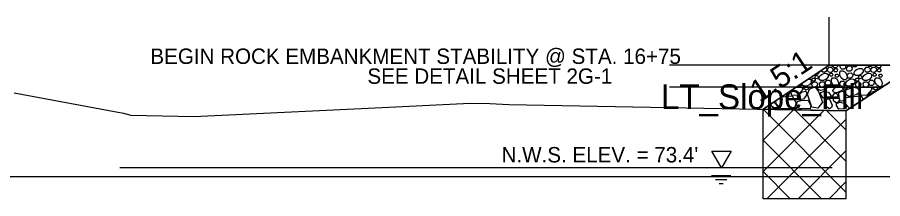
# Model space of a CAD drawing. Extents: x -14026 to 1303, y -10 to 9533.
# Drawn here: x 82.55 to 121.9, y 2999 to 3007.24 of the extents above; entities that cross this region are included whole.
import ezdxf

# ---------------------------------------------------------------- set-up
doc = ezdxf.new("R2010")
doc.units = 0
for name, color, linetype in [('Exist Cross Section Cell', 7, 'Continuous'), ('Exist XS Ground Line', 7, 'Continuous'), ('Old_Level_10', 7, 'Continuous'), ('Prop XS Side Slope Text', 7, 'Continuous'), ('Scratch_Level_0', 7, 'Continuous'), ('Scratch_Level_1', 7, 'Continuous'), ('Scratch_Level_3', 7, 'Continuous'), ('Scratch_Level_5', 7, 'Continuous')]:
    doc.layers.add(name, color=color, linetype=linetype)

msp = doc.modelspace()

# ---------------------------------------------------------------- linework, layer by layer
at = {"layer": 'Exist Cross Section Cell'}
msp.add_line((0, 3000), (150, 3000), dxfattribs=at)
at = {"layer": 'Exist XS Ground Line'}
msp.add_lwpolyline([(82.41, 3003.808), (87.387, 3002.891), (87.708, 3002.797), (90.58, 3002.733), (99.144, 3003.149), (103.146, 3003.333), (104.045, 3003.328), (104.909, 3003.285), (120.234, 3002.995), (122.366, 3004.389)], dxfattribs=at)
at = {"layer": 'Old_Level_10'}
for p, q in [((119.976, 3005.021), (120.008, 3005.067)), ((117.689, 3003.879), (117.714, 3003.824)), ((117.97, 3004.067), (121.872, 3004.067)), ((120.001, 3003), (120.001, 3003))]:
    msp.add_line(p, q, dxfattribs=at)
msp.add_lwpolyline([(116.47, 3003.067), (119.47, 3005.067), (123.495, 3005.067), (122.366, 3004.389), (120.234, 3002.995)], close=True, dxfattribs=at)
for points in [[(119.307, 3004.958), (119.36, 3004.903), (119.35, 3004.794), (119.283, 3004.739), (119.177, 3004.747), (119.127, 3004.795), (119.12, 3004.833)], [(119.417, 3005.031), (119.392, 3005.005), (119.378, 3005.006)], [(119.388, 3004.874), (119.455, 3004.97), (119.562, 3004.976), (119.637, 3004.899), (119.626, 3004.79), (119.56, 3004.735), (119.454, 3004.743), (119.404, 3004.791), (119.388, 3004.874)], [(119.849, 3005.067), (119.843, 3004.999), (119.791, 3004.944), (119.697, 3004.946), (119.591, 3005.029), (119.572, 3005.067)], [(120.204, 3005.067), (120.225, 3005.045), (120.214, 3004.937), (120.148, 3004.881), (120.042, 3004.889), (119.992, 3004.938), (119.976, 3005.021)], [(120.26, 3004.926), (120.327, 3005.021), (120.434, 3005.027), (120.509, 3004.95), (120.498, 3004.842), (120.432, 3004.787), (120.326, 3004.794), (120.276, 3004.843), (120.26, 3004.926)], [(120.742, 3005.067), (120.74, 3005.044), (120.688, 3004.989), (120.594, 3004.991), (120.497, 3005.067)], [(121.012, 3005.067), (120.993, 3005.051), (120.887, 3005.059), (120.879, 3005.067)], [(121.09, 3004.878), (121.157, 3004.974), (121.264, 3004.98), (121.339, 3004.903), (121.328, 3004.794), (121.262, 3004.739), (121.156, 3004.747), (121.106, 3004.795), (121.09, 3004.878)], [(121.424, 3005.067), (121.423, 3005.06), (121.371, 3005.005), (121.277, 3005.007), (121.201, 3005.067)], [(121.366, 3004.874), (121.434, 3004.97), (121.541, 3004.976), (121.616, 3004.899), (121.605, 3004.79), (121.539, 3004.735), (121.433, 3004.743), (121.383, 3004.791), (121.367, 3004.874)], [(121.828, 3005.067), (121.822, 3004.999), (121.77, 3004.944), (121.676, 3004.946), (121.569, 3005.029), (121.551, 3005.067)], [(119.031, 3004.774), (119.031, 3004.763), (118.947, 3004.657), (118.819, 3004.593), (118.757, 3004.591)], [(118.827, 3004.533), (118.867, 3004.59), (118.931, 3004.594), (118.976, 3004.547), (118.97, 3004.482), (118.93, 3004.449), (118.866, 3004.454), (118.836, 3004.483), (118.827, 3004.533)], [(119.126, 3004.645), (119.252, 3004.695), (119.368, 3004.685), (119.423, 3004.633), (119.421, 3004.539), (119.338, 3004.432), (119.209, 3004.368), (119.087, 3004.366), (119.019, 3004.414), (119.013, 3004.511), (119.068, 3004.597), (119.131, 3004.648)], [(119.486, 3004.643), (119.526, 3004.7), (119.59, 3004.704), (119.635, 3004.658), (119.629, 3004.593), (119.589, 3004.559), (119.525, 3004.564), (119.495, 3004.593), (119.486, 3004.643)], [(119.694, 3004.845), (119.734, 3004.902), (119.798, 3004.906), (119.843, 3004.859), (119.837, 3004.794), (119.797, 3004.761), (119.733, 3004.766), (119.703, 3004.795), (119.694, 3004.845)], [(119.75, 3004.596), (119.791, 3004.653), (119.855, 3004.657), (119.9, 3004.61), (119.893, 3004.545), (119.854, 3004.512), (119.79, 3004.517), (119.76, 3004.546), (119.75, 3004.596)], [(120.232, 3004.7), (120.282, 3004.574), (120.272, 3004.458), (120.22, 3004.403), (120.126, 3004.405), (120.02, 3004.488), (119.955, 3004.617), (119.953, 3004.739), (120.002, 3004.807), (120.099, 3004.813), (120.185, 3004.758), (120.236, 3004.694)], [(120.29, 3004.611), (120.357, 3004.707), (120.464, 3004.713), (120.539, 3004.635), (120.528, 3004.527), (120.462, 3004.472), (120.356, 3004.48), (120.306, 3004.528), (120.29, 3004.611)], [(120.715, 3004.87), (120.841, 3004.919), (120.956, 3004.909), (121.011, 3004.857), (121.009, 3004.763), (120.926, 3004.657), (120.797, 3004.593), (120.676, 3004.59), (120.608, 3004.639), (120.601, 3004.736), (120.657, 3004.822), (120.72, 3004.873)], [(120.805, 3004.533), (120.846, 3004.59), (120.91, 3004.594), (120.955, 3004.547), (120.948, 3004.482), (120.909, 3004.449), (120.845, 3004.454), (120.815, 3004.483), (120.805, 3004.533)], [(121.105, 3004.645), (121.231, 3004.695), (121.346, 3004.685), (121.401, 3004.633), (121.4, 3004.539), (121.316, 3004.432), (121.187, 3004.368), (121.066, 3004.366), (120.998, 3004.414), (120.991, 3004.511), (121.047, 3004.597), (121.11, 3004.648)], [(121.464, 3004.643), (121.505, 3004.7), (121.569, 3004.704), (121.614, 3004.658), (121.607, 3004.593), (121.568, 3004.559), (121.504, 3004.564), (121.474, 3004.593), (121.464, 3004.643)], [(121.672, 3004.845), (121.713, 3004.902), (121.777, 3004.906), (121.822, 3004.859), (121.815, 3004.794), (121.776, 3004.761), (121.712, 3004.766), (121.682, 3004.795), (121.672, 3004.845)], [(121.729, 3004.596), (121.769, 3004.653), (121.834, 3004.657), (121.879, 3004.61), (121.872, 3004.545), (121.832, 3004.512), (121.769, 3004.517), (121.739, 3004.546), (121.729, 3004.596)], [(118.216, 3004.23), (118.209, 3004.157), (118.142, 3004.102), (118.036, 3004.11), (118.036, 3004.11)], [(118.523, 3004.435), (118.599, 3004.429), (118.654, 3004.376), (118.652, 3004.283), (118.569, 3004.176), (118.44, 3004.112), (118.319, 3004.11), (118.25, 3004.158), (118.244, 3004.249)], [(118.684, 3004.206), (118.751, 3004.301), (118.858, 3004.308), (118.933, 3004.23), (118.922, 3004.122), (118.856, 3004.067), (118.75, 3004.074), (118.7, 3004.123), (118.684, 3004.206)], [(118.688, 3004.416), (118.728, 3004.473), (118.793, 3004.477), (118.838, 3004.431), (118.831, 3004.366), (118.791, 3004.332), (118.728, 3004.337), (118.698, 3004.366), (118.688, 3004.416)], [(119.03, 3004.21), (119.098, 3004.305), (119.205, 3004.311), (119.28, 3004.234), (119.269, 3004.126), (119.202, 3004.071), (119.096, 3004.078), (119.047, 3004.127), (119.03, 3004.21)], [(119.291, 3004.28), (119.358, 3004.376), (119.466, 3004.382), (119.54, 3004.304), (119.53, 3004.196), (119.463, 3004.141), (119.357, 3004.148), (119.307, 3004.197), (119.291, 3004.28)], [(119.852, 3004.382), (119.902, 3004.257), (119.892, 3004.141), (119.84, 3004.086), (119.746, 3004.088), (119.639, 3004.171), (119.575, 3004.3), (119.573, 3004.421), (119.621, 3004.49), (119.718, 3004.496), (119.805, 3004.441), (119.855, 3004.377)], [(119.949, 3004.241), (120.016, 3004.337), (120.123, 3004.343), (120.198, 3004.266), (120.187, 3004.157), (120.121, 3004.102), (120.015, 3004.11), (119.965, 3004.158), (119.949, 3004.241)], [(120.337, 3004.389), (120.462, 3004.439), (120.578, 3004.429), (120.633, 3004.376), (120.631, 3004.283), (120.548, 3004.176), (120.419, 3004.112), (120.298, 3004.11), (120.229, 3004.158), (120.223, 3004.255), (120.278, 3004.341), (120.342, 3004.392)], [(120.662, 3004.206), (120.729, 3004.301), (120.837, 3004.308), (120.911, 3004.23), (120.901, 3004.122), (120.834, 3004.067), (120.728, 3004.074), (120.678, 3004.123), (120.662, 3004.206)], [(120.667, 3004.416), (120.707, 3004.473), (120.771, 3004.477), (120.816, 3004.431), (120.81, 3004.366), (120.77, 3004.332), (120.706, 3004.337), (120.676, 3004.366), (120.667, 3004.416)], [(121.009, 3004.21), (121.076, 3004.305), (121.184, 3004.311), (121.258, 3004.234), (121.247, 3004.126), (121.181, 3004.071), (121.075, 3004.078), (121.025, 3004.127), (121.009, 3004.21)], [(121.27, 3004.28), (121.337, 3004.376), (121.444, 3004.382), (121.519, 3004.304), (121.508, 3004.196), (121.442, 3004.141), (121.336, 3004.148), (121.286, 3004.197), (121.27, 3004.28)], [(121.831, 3004.382), (121.881, 3004.257), (121.871, 3004.141), (121.818, 3004.086), (121.725, 3004.088), (121.618, 3004.171), (121.554, 3004.3), (121.552, 3004.421), (121.6, 3004.49), (121.697, 3004.496), (121.783, 3004.441), (121.834, 3004.377)], [(117.714, 3003.824), (117.549, 3003.723), (117.403, 3003.689)], [(118.227, 3004.067), (118.266, 3003.96), (118.039, 3003.707), (117.777, 3003.69), (117.717, 3003.898)], [(118.454, 3003.817), (118.43, 3003.687), (118.297, 3003.518), (118.12, 3003.509), (118.022, 3003.639), (118.243, 3003.846), (118.395, 3003.89), (118.454, 3003.817)], [(118.416, 3003.922), (118.319, 3004), (118.294, 3004.067)], [(118.551, 3004.067), (118.526, 3003.983), (118.416, 3003.922)], [(118.828, 3004.06), (118.992, 3003.866), (119.174, 3003.386), (118.948, 3003.108), (118.683, 3003.153), (118.49, 3003.74), (118.575, 3003.968), (118.766, 3004.067)], [(119.41, 3004.067), (119.299, 3003.963), (119.082, 3003.911), (118.941, 3003.993), (118.935, 3004.067)], [(119.089, 3003.825), (119.237, 3003.887), (119.445, 3003.845), (119.545, 3003.68), (119.493, 3003.584), (119.193, 3003.566), (119.093, 3003.731), (119.089, 3003.825)], [(119.809, 3003.339), (119.686, 3003.422), (119.62, 3003.663), (119.722, 3003.786), (119.816, 3003.771), (119.933, 3003.501), (119.9, 3003.406), (119.809, 3003.339)], [(119.632, 3003.914), (119.733, 3004.036), (119.772, 3004.067)], [(120.065, 3004.067), (120.106, 3003.945), (119.819, 3003.803), (119.667, 3003.834), (119.632, 3003.914)], [(119.982, 3003.409), (119.921, 3003.563), (119.915, 3003.818), (120.049, 3003.877), (120.133, 3003.854), (120.172, 3003.531), (120.087, 3003.438), (119.982, 3003.409)], [(120.172, 3003.962), (120.131, 3004.054), (120.125, 3004.067)], [(120.335, 3004.067), (120.282, 3004.023), (120.172, 3003.962)], [(120.862, 3003.824), (120.697, 3003.723), (120.344, 3003.64), (120.188, 3003.784), (120.182, 3003.934), (120.577, 3004.067)], [(120.592, 3004.067), (120.772, 3004.026), (120.862, 3003.824)], [(121.375, 3004.067), (121.414, 3003.96), (121.186, 3003.707), (120.924, 3003.69), (120.817, 3004.067)], [(121.17, 3003.639), (121.17, 3003.639), (121.391, 3003.846), (121.543, 3003.89), (121.556, 3003.874)], [(121.564, 3003.922), (121.467, 3004), (121.442, 3004.067)], [(121.698, 3004.067), (121.674, 3003.983), (121.564, 3003.922)], [(116.917, 3003.364), (117.011, 3003.345), (117.118, 3003.181), (117.065, 3003.085), (116.766, 3003.067), (116.674, 3003.203)], [(117.318, 3003.632), (117.782, 3003.675), (117.977, 3003.332), (117.881, 3003.084), (117.28, 3003.085), (117.058, 3003.314), (117.049, 3003.453)], [(118.016, 3003.415), (118.195, 3003.46), (118.513, 3003.479), (118.63, 3003.221), (118.599, 3003.076), (118.128, 3003.101), (118.004, 3003.246), (118.016, 3003.415)], [(119.479, 3003.081), (119.357, 3003.164), (119.29, 3003.405), (119.392, 3003.528), (119.486, 3003.513), (119.604, 3003.243), (119.57, 3003.147), (119.479, 3003.081)], [(119.803, 3003.318), (119.95, 3003.387), (120.158, 3003.345), (120.265, 3003.181), (120.213, 3003.085), (119.913, 3003.067), (119.807, 3003.225), (119.803, 3003.318)], [(120.189, 3003.576), (120.443, 3003.63), (120.929, 3003.675), (121.006, 3003.539)], [(120.383, 3003.131), (120.206, 3003.314), (120.189, 3003.576)], [(117.22, 3003.052), (117.247, 3003.067), (117.281, 3003.051)], [(117.638, 3003.044), (117.73, 3003.062), (117.859, 3003.04)], [(118.049, 3003.037), (118.067, 3003.054), (118.216, 3003.055), (118.229, 3003.033)], [(118.805, 3003.022), (118.822, 3003.031), (118.854, 3003.021)]]:
    msp.add_lwpolyline(points, dxfattribs=at)
at = {"layer": 'Prop XS Side Slope Text'}
for p, q in [((114.122, 3000.046), (114.997, 3000.046)), ((114.297, 2999.871), (114.822, 2999.871)), ((114.472, 2999.696), (114.647, 2999.696))]:
    msp.add_line(p, q, dxfattribs=at)
msp.add_lwpolyline([(114.136, 3001.159), (115.011, 3001.159), (114.573, 3000.4)], close=True, dxfattribs=at)
at = {"layer": 'Scratch_Level_1'}
msp.add_line((119.611, 3000.4), (87.209, 3000.4), dxfattribs=at)
at = {"layer": 'Scratch_Level_3'}
for p, q in [((119.47, 3005.067), (119.47, 3007.238)), ((123.495, 3005.067), (112.204, 3005.067)), ((119.47, 3005.067), (116.47, 3003.067)), ((121.872, 3004.067), (112.204, 3004.067))]:
    msp.add_line(p, q, dxfattribs=at)
at = {"layer": 'Scratch_Level_5'}
for p, q in [((116.464, 3003.067), (120.234, 2999.297)), ((116.464, 3001.652), (117.852, 3003.04)), ((116.464, 3000.238), (119.24, 3003.014)), ((117.906, 3003.039), (120.234, 3000.711)), ((119.347, 3003.012), (120.234, 3002.125)), ((116.64, 2999), (120.234, 3002.594)), ((116.464, 3001.652), (119.117, 2999)), ((118.054, 2999), (120.234, 3001.18)), ((116.464, 3000.238), (117.702, 2999)), ((119.469, 2999), (120.234, 2999.765))]:
    msp.add_line(p, q, dxfattribs=at)
msp.add_lwpolyline([(120.234, 3002.995), (120.234, 2999), (116.464, 2999), (116.464, 3003.067)], close=True, dxfattribs=at)

# ---------------------------------------------------------------- texts
at = {"layer": 'Old_Level_10'}
for s, p in [('BEGIN ROCK EMBANKMENT STABILITY @ STA. 16+75', (88.604, 3005.12)), ('SEE DETAIL SHEET 2G-1', (98.473, 3004.217))]:
    msp.add_text(s, height=0.7, dxfattribs=at).set_placement(p)
at = {"layer": 'Prop XS Side Slope Text'}
msp.add_text('1.5:1', height=1, rotation=33.6901, dxfattribs=at).set_placement((116.303, 3003.337))
msp.add_text("N.W.S. ELEV. = 73.4'", height=0.7, dxfattribs=at).set_placement((104.573, 3000.646))
at = {"layer": 'Scratch_Level_0'}
msp.add_text('LT_Slope_Fill', height=1.125, dxfattribs=at).set_placement((111.824, 3003.067))

doc.saveas('drawing.dxf')
